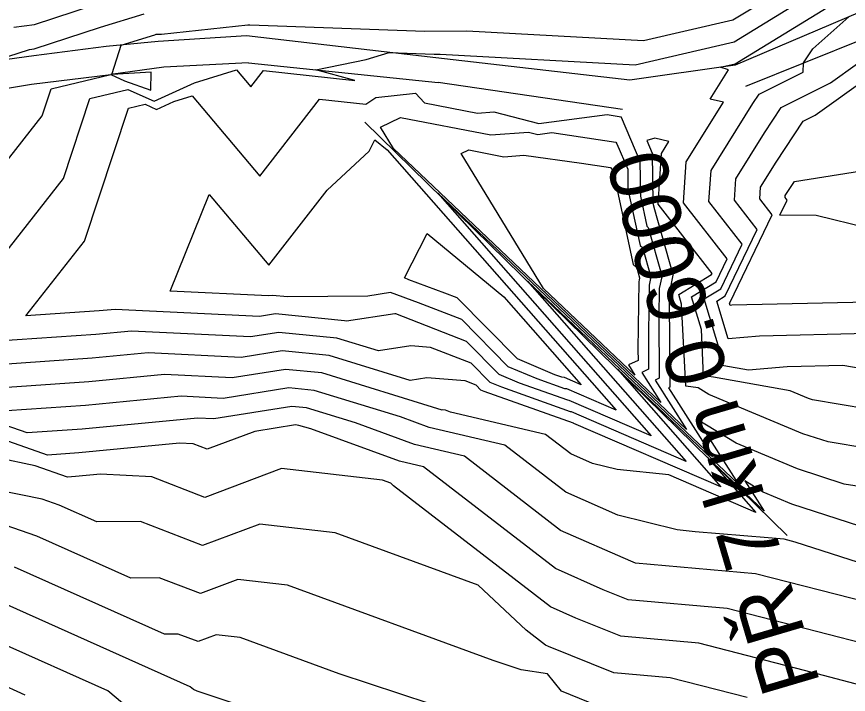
# Model space of a CAD drawing. Extents: x -549394 to -546608, y -1037055 to -1033629.
# Drawn here: x -547944.9 to -547816.2, y -1035642.2 to -1035537.3 of the extents above; entities that cross this region are included whole.
import ezdxf

# ---------------------------------------------------------------- set-up
doc = ezdxf.new("R2010")
doc.units = 0
for name, color, linetype in [('hlavni_vrst', 7, 'Continuous'), ('hrana_L', 7, 'Continuous'), ('norm_vrst', 7, 'Continuous'), ('x_popis_pricne_rezy_C1', 7, 'Continuous')]:
    doc.layers.add(name, color=color, linetype=linetype)

msp = doc.modelspace()

# ---------------------------------------------------------------- linework, layer by layer
at = {"layer": 'hlavni_vrst'}
for p, q in [((-547833.67, -1035544.62), (-547816.24, -1035533.92)), ((-547837.57, -1035550.06), (-547834.74, -1035545.54)), ((-547835.99, -1035545.15), (-547833.67, -1035544.62)), ((-547834.74, -1035545.54), (-547835.99, -1035545.15)), ((-547889.33, -1035549.83), (-547883.16, -1035549.18)), ((-547883.16, -1035549.18), (-547881.77, -1035550.67)), ((-547923.29, -1035551.66), (-547920.56, -1035550.43)), ((-547920.56, -1035550.43), (-547917.73, -1035549.55)), ((-547917.73, -1035549.55), (-547907.28, -1035562)), ((-547907.28, -1035562), (-547898.01, -1035550.06)), ((-547898.01, -1035550.06), (-547890.88, -1035550.84)), ((-547890.88, -1035550.84), (-547889.33, -1035549.83)), ((-547881.77, -1035550.67), (-547873.55, -1035552.25)), ((-547841.25, -1035559.8), (-547835.48, -1035550.56)), ((-547835.48, -1035550.56), (-547837.57, -1035550.06)), ((-547934.4, -1035572.05), (-547927.62, -1035551.49)), ((-547927.62, -1035551.49), (-547925.04, -1035550.88)), ((-547925.04, -1035550.88), (-547923.29, -1035551.66)), ((-547873.55, -1035552.25), (-547871.03, -1035552.06)), ((-547871.03, -1035552.06), (-547864.06, -1035553.84)), ((-547864.06, -1035553.84), (-547853.52, -1035552.48)), ((-547853.52, -1035552.48), (-547851.35, -1035552.8)), ((-547851.35, -1035552.8), (-547851.32, -1035552.85)), ((-547851.32, -1035552.85), (-547848.42, -1035559.69)), ((-547848.42, -1035559.69), (-547848.34, -1035565.11)), ((-547841.66, -1035566.13), (-547841.25, -1035559.8)), ((-547879.73, -1035564.66), (-547846.71, -1035602.21)), ((-547841.2, -1035601.24), (-547879.73, -1035564.66)), ((-547848.34, -1035565.11), (-547847.35, -1035569.75)), ((-547834.93, -1035574.81), (-547841.66, -1035566.13)), ((-547847.35, -1035569.75), (-547847.14, -1035569.93)), ((-547847.14, -1035569.93), (-547845.03, -1035577.41)), ((-547943.47, -1035583.64), (-547934.4, -1035572.05)), ((-547836.63, -1035578.35), (-547834.93, -1035574.81)), ((-547845.06, -1035577.58), (-547845.44, -1035579.42)), ((-547845.03, -1035577.41), (-547845.06, -1035577.58)), ((-547840.46, -1035580.67), (-547836.63, -1035578.35)), ((-547845.44, -1035579.42), (-547845.5, -1035583.76)), ((-547838.92, -1035585.75), (-547840.46, -1035580.67)), ((-547932.16, -1035582.87), (-547943.47, -1035583.64)), ((-547929.67, -1035582.63), (-547932.16, -1035582.87)), ((-547907.32, -1035583.73), (-547929.67, -1035582.63)), ((-547904.86, -1035583.34), (-547907.32, -1035583.73)), ((-547894.15, -1035584.38), (-547904.86, -1035583.34)), ((-547886.37, -1035583.33), (-547893.84, -1035584.47)), ((-547886.2, -1035583.34), (-547886.37, -1035583.33)), ((-547875.26, -1035587.6), (-547886.2, -1035583.34)), ((-547845.5, -1035583.76), (-547845.43, -1035593.29)), ((-547893.84, -1035584.47), (-547894.15, -1035584.38)), ((-547838.57, -1035592.92), (-547838.92, -1035585.75)), ((-547870.22, -1035592.72), (-547875.26, -1035587.6)), ((-547867.08, -1035594.05), (-547870.22, -1035592.72)), ((-547837.06, -1035593.12), (-547838.57, -1035592.92)), ((-547825.17, -1035595.25), (-547837.06, -1035593.12)), ((-547859.6, -1035596.71), (-547867.08, -1035594.05)), ((-547845.43, -1035593.29), (-547846.07, -1035593.6)), ((-547846.07, -1035593.6), (-547841.2, -1035601.24)), ((-547943.29, -1035601.77), (-547961.77, -1035595.29)), ((-547822.34, -1035596.43), (-547825.17, -1035595.25)), ((-547859.39, -1035596.73), (-547859.6, -1035596.71)), ((-547846.71, -1035602.21), (-547859.39, -1035596.73)), ((-547821.72, -1035596.64), (-547822.34, -1035596.43)), ((-547805.21, -1035599.43), (-547821.72, -1035596.64)), ((-547902.29, -1035597.67), (-547914.37, -1035599.58)), ((-547900.05, -1035597.88), (-547902.29, -1035597.67)), ((-547892.44, -1035600.22), (-547900.05, -1035597.88)), ((-547916.9, -1035599.46), (-547934.77, -1035601.19)), ((-547914.37, -1035599.58), (-547916.9, -1035599.46)), ((-547883.35, -1035603.53), (-547892.44, -1035600.22)), ((-547934.77, -1035601.19), (-547943.29, -1035601.77)), ((-547875.61, -1035605.34), (-547883.35, -1035603.53)), ((-547860.7, -1035616.85), (-547875.61, -1035605.34)), ((-547849.86, -1035621.63), (-547860.7, -1035616.85)), ((-547922.03, -1035632.93), (-547945.25, -1035622.54)), ((-547849.11, -1035621.93), (-547849.86, -1035621.63)), ((-547830.53, -1035623.58), (-547849.11, -1035621.93)), ((-547812.93, -1035628.1), (-547830.53, -1035623.58)), ((-547919.9, -1035632.9), (-547922.03, -1035632.93)), ((-547916.84, -1035634.08), (-547919.9, -1035632.9)), ((-547914.03, -1035633.03), (-547916.84, -1035634.08)), ((-547910.33, -1035633.46), (-547914.03, -1035633.03)), ((-547895, -1035639.08), (-547910.33, -1035633.46)), ((-547876.12, -1035645.25), (-547895, -1035639.08))]:
    msp.add_line(p, q, dxfattribs=at)
at = {"layer": 'hrana_L'}
for p, q in [((-547814.39, -1035536.61), (-547833.66, -1035544.82)), ((-547909.34, -1035540.3), (-547923, -1035541.16)), ((-547880.04, -1035543.67), (-547909.34, -1035540.3)), ((-547923, -1035541.16), (-547931.07, -1035541.92)), ((-547832.01, -1035548.06), (-547813.58, -1035540.62)), ((-547931.07, -1035541.92), (-547942.25, -1035543.35)), ((-547942.25, -1035543.35), (-547972.47, -1035547.64)), ((-547849.99, -1035547.16), (-547880.04, -1035543.67)), ((-547922.15, -1035545.14), (-547930.35, -1035546.27)), ((-547909.02, -1035544.46), (-547922.15, -1035545.14)), ((-547909.02, -1035544.46), (-547879.65, -1035547.5)), ((-547833.66, -1035544.82), (-547849.99, -1035547.16)), ((-547942.64, -1035547.74), (-547930.35, -1035546.27)), ((-547971.54, -1035552.66), (-547942.64, -1035547.74)), ((-547851.13, -1035551.7), (-547879.65, -1035547.5)), ((-547890.99, -1035553.63), (-547825.64, -1035617.62))]:
    msp.add_line(p, q, dxfattribs=at)
at = {"layer": 'norm_vrst'}
for p, q in [((-547834.04, -1035537.81), (-547819.64, -1035528.97)), ((-547833.85, -1035541.21), (-547817.94, -1035531.44)), ((-547942.17, -1035538.52), (-547932.88, -1035535.5)), ((-547931.91, -1035538.93), (-547925.16, -1035536.89)), ((-547847.89, -1035541.02), (-547834.04, -1035537.81)), ((-547821.64, -1035542.31), (-547816.07, -1035537.33)), ((-547945.36, -1035538.96), (-547942.17, -1035538.52)), ((-547942.23, -1035542.29), (-547931.91, -1035538.93)), ((-547922.51, -1035540.04), (-547909.14, -1035538.57)), ((-547909.14, -1035538.57), (-547908.8, -1035538.55)), ((-547908.8, -1035538.55), (-547881.74, -1035539.58)), ((-547928.74, -1035541.7), (-547923.52, -1035540.13)), ((-547923.52, -1035540.13), (-547923.31, -1035540.03)), ((-547923.31, -1035540.03), (-547922.51, -1035540.04)), ((-547881.74, -1035539.58), (-547875.22, -1035539.51)), ((-547875.22, -1035539.51), (-547847.89, -1035541.02)), ((-547849.17, -1035544.77), (-547833.85, -1035541.21)), ((-547948.71, -1035544.27), (-547942.93, -1035542.39)), ((-547942.93, -1035542.39), (-547942.23, -1035542.29)), ((-547930.13, -1035546.12), (-547928.74, -1035541.7)), ((-547890.82, -1035543.96), (-547887.25, -1035542.84)), ((-547887.25, -1035542.84), (-547880.27, -1035543.11)), ((-547823.1, -1035544.46), (-547821.64, -1035542.31)), ((-547898.59, -1035545.54), (-547890.82, -1035543.96)), ((-547880.27, -1035543.11), (-547879.37, -1035543.1)), ((-547879.37, -1035543.1), (-547849.17, -1035544.77)), ((-547917.38, -1035547.56), (-547910.87, -1035545.54)), ((-547910.87, -1035545.54), (-547908.65, -1035548.19)), ((-547892.57, -1035547.19), (-547898.59, -1035545.54)), ((-547823.16, -1035545.88), (-547823.1, -1035544.46)), ((-547821.28, -1035552.58), (-547810.32, -1035544.67)), ((-547818.92, -1035547.58), (-547814.73, -1035544.55)), ((-547939.59, -1035548.5), (-547930.32, -1035546.29)), ((-547930.32, -1035546.29), (-547928.24, -1035547.23)), ((-547930.12, -1035546.24), (-547930.13, -1035546.12)), ((-547924.1, -1035545.88), (-547930.12, -1035546.24)), ((-547924.12, -1035548.71), (-547924.1, -1035545.88)), ((-547908.65, -1035548.19), (-547906.68, -1035545.65)), ((-547906.68, -1035545.65), (-547892.57, -1035547.19)), ((-547829.99, -1035549.3), (-547823.16, -1035545.88)), ((-547928.24, -1035547.23), (-547924.12, -1035548.71)), ((-547923.65, -1035550.39), (-547917.38, -1035547.56)), ((-547826.56, -1035551.4), (-547818.92, -1035547.58)), ((-547940.97, -1035552.68), (-547939.59, -1035548.5)), ((-547933.6, -1035550), (-547927.68, -1035548.58)), ((-547927.68, -1035548.58), (-547923.65, -1035550.39)), ((-547830.95, -1035550.75), (-547829.99, -1035549.3)), ((-547937.68, -1035562.37), (-547933.6, -1035550)), ((-547837.42, -1035561.11), (-547830.95, -1035550.75)), ((-547829.15, -1035555.3), (-547826.56, -1035551.4)), ((-547946.89, -1035560.24), (-547940.97, -1035552.68)), ((-547888.61, -1035554.41), (-547885.5, -1035552.93)), ((-547885.5, -1035552.93), (-547871.52, -1035555.62)), ((-547823.14, -1035553.51), (-547821.28, -1035552.58)), ((-547886.58, -1035557.74), (-547888.61, -1035554.41)), ((-547827.35, -1035559.85), (-547823.14, -1035553.51)), ((-547871.52, -1035555.62), (-547865.67, -1035555.19)), ((-547865.67, -1035555.19), (-547864.24, -1035555.55)), ((-547864.24, -1035555.55), (-547862.06, -1035555.27)), ((-547862.06, -1035555.27), (-547852.16, -1035556.74)), ((-547833.6, -1035562.41), (-547829.15, -1035555.3)), ((-547890.33, -1035558.11), (-547889.45, -1035556.38)), ((-547889.45, -1035556.38), (-547887.56, -1035557.95)), ((-547852.16, -1035556.74), (-547851.99, -1035556.98)), ((-547851.99, -1035556.98), (-547850.32, -1035560.9)), ((-547846.12, -1035556.12), (-547847.35, -1035556.5)), ((-547847.35, -1035556.5), (-547846.52, -1035558.47)), ((-547843.93, -1035556.65), (-547846.12, -1035556.12)), ((-547845.08, -1035558.5), (-547843.93, -1035556.65)), ((-547896.86, -1035564.16), (-547890.33, -1035558.11)), ((-547887.56, -1035557.95), (-547852.12, -1035598.25)), ((-547845.2, -1035597.03), (-547886.58, -1035557.74)), ((-547876.09, -1035558.52), (-547874.89, -1035557.95)), ((-547874.89, -1035557.95), (-547869.48, -1035558.99)), ((-547863.36, -1035579.38), (-547876.09, -1035558.52)), ((-547869.48, -1035558.99), (-547866.4, -1035558.76)), ((-547866.4, -1035558.76), (-547857.46, -1035560.01)), ((-547846.52, -1035558.47), (-547846.41, -1035566.21)), ((-547845.59, -1035566.33), (-547845.08, -1035558.5)), ((-547857.46, -1035560.01), (-547852.96, -1035560.68)), ((-547852.96, -1035560.68), (-547852.66, -1035561.1)), ((-547850.32, -1035560.9), (-547850.28, -1035564.02)), ((-547829.77, -1035563.72), (-547827.35, -1035559.85)), ((-547824.52, -1035562.85), (-547809.54, -1035560.47)), ((-547852.66, -1035561.1), (-547852.22, -1035562.12)), ((-547852.22, -1035562.12), (-547852.21, -1035562.92)), ((-547837.74, -1035565.92), (-547837.42, -1035561.11)), ((-547955.22, -1035584.76), (-547937.68, -1035562.37)), ((-547852.21, -1035562.92), (-547849.47, -1035575.7)), ((-547833.81, -1035565.72), (-547833.6, -1035562.41)), ((-547825.55, -1035564.4), (-547824.52, -1035562.85)), ((-547921.14, -1035579.81), (-547915.12, -1035564.83)), ((-547915.12, -1035564.83), (-547905.9, -1035575.8)), ((-547905.9, -1035575.8), (-547896.86, -1035564.16)), ((-547850.28, -1035564.02), (-547848.41, -1035572.73)), ((-547829.88, -1035565.51), (-547829.77, -1035563.72)), ((-547825.94, -1035565.02), (-547825.55, -1035564.4)), ((-547832.61, -1035572.53), (-547837.74, -1035565.92)), ((-547830.29, -1035570.26), (-547833.81, -1035565.72)), ((-547827.97, -1035567.98), (-547829.88, -1035565.51)), ((-547826.77, -1035568.03), (-547825.65, -1035565.7)), ((-547825.96, -1035565.31), (-547825.94, -1035565.02)), ((-547825.65, -1035565.7), (-547825.96, -1035565.31)), ((-547846.41, -1035566.21), (-547846.29, -1035566.78)), ((-547846.29, -1035566.78), (-547846.26, -1035566.8)), ((-547846.26, -1035566.8), (-547843.31, -1035577.25)), ((-547837.25, -1035577.09), (-547845.59, -1035566.33)), ((-547834.5, -1035581.64), (-547827.97, -1035567.98)), ((-547821.16, -1035568.08), (-547826.77, -1035568.03)), ((-547799.43, -1035573.39), (-547821.16, -1035568.08)), ((-547884.85, -1035577.74), (-547881.35, -1035570.87)), ((-547881.35, -1035570.87), (-547869.51, -1035580.68)), ((-547835.21, -1035580.55), (-547830.29, -1035570.26)), ((-547835.92, -1035579.45), (-547832.61, -1035572.53)), ((-547848.41, -1035572.73), (-547848.02, -1035573.07)), ((-547848.02, -1035573.07), (-547846.75, -1035577.58)), ((-547849.47, -1035575.7), (-547848.9, -1035576.2)), ((-547848.9, -1035576.2), (-547848.47, -1035577.74)), ((-547884.22, -1035578.06), (-547884.85, -1035577.74)), ((-547848.47, -1035577.74), (-547848.53, -1035578.11)), ((-547846.75, -1035577.58), (-547846.8, -1035577.84)), ((-547843.33, -1035577.31), (-547843.86, -1035579.97)), ((-547843.31, -1035577.25), (-547843.33, -1035577.31)), ((-547842.42, -1035580.33), (-547837.33, -1035577.25)), ((-547837.33, -1035577.25), (-547837.25, -1035577.09)), ((-547878.63, -1035580.1), (-547884.22, -1035578.06)), ((-547865.82, -1035578.27), (-547841.29, -1035606.17)), ((-547837.2, -1035605.45), (-547865.82, -1035578.27)), ((-547848.58, -1035578.33), (-547848.74, -1035588.82)), ((-547848.53, -1035578.11), (-547848.58, -1035578.33)), ((-547847.01, -1035578.88), (-547847.12, -1035586.29)), ((-547846.8, -1035577.84), (-547847.01, -1035578.88)), ((-547905.91, -1035580.56), (-547921.14, -1035579.81)), ((-547887.03, -1035580.03), (-547890.54, -1035580.58)), ((-547882.7, -1035581.61), (-547887.03, -1035580.03)), ((-547876.71, -1035580.84), (-547878.63, -1035580.1)), ((-547849.2, -1035592.82), (-547863.36, -1035579.38)), ((-547843.86, -1035579.97), (-547843.88, -1035581.23)), ((-547838.5, -1035581.01), (-547835.92, -1035579.45)), ((-547905.38, -1035580.47), (-547905.91, -1035580.56)), ((-547902.92, -1035580.71), (-547905.38, -1035580.47)), ((-547890.54, -1035580.58), (-547902.92, -1035580.71)), ((-547875.98, -1035584.22), (-547882.7, -1035581.61)), ((-547867.4, -1035590.31), (-547876.71, -1035580.84)), ((-547869.51, -1035580.68), (-547857.54, -1035594.29)), ((-547843.88, -1035581.23), (-547843.78, -1035594.66)), ((-547841.97, -1035581.81), (-547842.42, -1035580.33)), ((-547835.87, -1035589.7), (-547838.5, -1035581.01)), ((-547836.54, -1035581.35), (-547835.21, -1035580.55)), ((-547834.78, -1035587.18), (-547836.54, -1035581.35)), ((-547804.25, -1035581.28), (-547834.2, -1035582)), ((-547841.34, -1035594.53), (-547841.97, -1035581.81)), ((-547834.58, -1035581.69), (-547834.5, -1035581.64)), ((-547834.48, -1035582.02), (-547834.58, -1035581.69)), ((-547834.2, -1035582), (-547834.48, -1035582.02)), ((-547868.81, -1035591.52), (-547875.98, -1035584.22)), ((-547932.68, -1035586.53), (-547955.84, -1035588.11)), ((-547927.12, -1035585.99), (-547932.68, -1035586.53)), ((-547908.73, -1035586.9), (-547927.12, -1035585.99)), ((-547904.35, -1035586.2), (-547908.73, -1035586.9)), ((-547895.33, -1035587.08), (-547904.35, -1035586.2)), ((-547847.12, -1035586.29), (-547847.08, -1035591.91)), ((-547810.63, -1035586.31), (-547829.92, -1035586.77)), ((-547888.9, -1035589.05), (-547895.33, -1035587.08)), ((-547829.92, -1035586.77), (-547834.78, -1035587.18)), ((-547903.83, -1035589.07), (-547910.14, -1035590.07)), ((-547896.51, -1035589.78), (-547903.83, -1035589.07)), ((-547883.89, -1035588.29), (-547888.9, -1035589.05)), ((-547880.83, -1035588.52), (-547883.89, -1035588.29)), ((-547874.53, -1035590.98), (-547880.83, -1035588.52)), ((-547848.74, -1035588.82), (-547848.72, -1035590.54)), ((-547933.2, -1035590.2), (-547952.71, -1035591.53)), ((-547924.56, -1035589.36), (-547933.2, -1035590.2)), ((-547910.14, -1035590.07), (-547924.56, -1035589.36)), ((-547883.97, -1035593.63), (-547896.51, -1035589.78)), ((-547861.6, -1035592.76), (-547867.4, -1035590.31)), ((-547848.72, -1035590.54), (-547850.21, -1035591.24)), ((-547835.79, -1035591.31), (-547835.87, -1035589.7)), ((-547871.62, -1035593.93), (-547874.53, -1035590.98)), ((-547864.34, -1035593.4), (-547868.81, -1035591.52)), ((-547851.92, -1035591.89), (-547835.88, -1035610.13)), ((-547833.2, -1035609.66), (-547851.92, -1035591.89)), ((-547850.21, -1035591.24), (-547849.2, -1035592.82)), ((-547847.08, -1035591.91), (-547848.14, -1035592.42)), ((-547835.46, -1035591.35), (-547835.79, -1035591.31)), ((-547831.61, -1035592.04), (-547835.46, -1035591.35)), ((-547825.65, -1035591.54), (-547831.61, -1035592.04)), ((-547817.01, -1035591.33), (-547825.65, -1035591.54)), ((-547804.58, -1035593.43), (-547817.01, -1035591.33)), ((-547922.01, -1035592.72), (-547933.72, -1035593.86)), ((-547911.55, -1035593.24), (-547922.01, -1035592.72)), ((-547903.32, -1035591.94), (-547911.55, -1035593.24)), ((-547897.69, -1035592.48), (-547903.32, -1035591.94)), ((-547879.03, -1035598.22), (-547897.69, -1035592.48)), ((-547860.52, -1035593.15), (-547861.6, -1035592.76)), ((-547860.12, -1035593.18), (-547860.52, -1035593.15)), ((-547857.54, -1035594.29), (-547860.12, -1035593.18)), ((-547848.14, -1035592.42), (-547845.2, -1035597.03)), ((-547933.72, -1035593.86), (-547949.57, -1035594.94)), ((-547881.41, -1035593.24), (-547883.97, -1035593.63)), ((-547875.47, -1035593.7), (-547881.41, -1035593.24)), ((-547873.8, -1035594.35), (-547875.47, -1035593.7)), ((-547873.03, -1035595.14), (-547873.8, -1035594.35)), ((-547869.82, -1035594.69), (-547871.62, -1035593.93)), ((-547860.06, -1035594.93), (-547864.34, -1035593.4)), ((-547902.8, -1035594.8), (-547912.96, -1035596.41)), ((-547898.87, -1035595.18), (-547902.8, -1035594.8)), ((-547885.5, -1035599.29), (-547898.87, -1035595.18)), ((-547872.55, -1035595.34), (-547873.03, -1035595.14)), ((-547858.69, -1035600.27), (-547872.55, -1035595.34)), ((-547859.15, -1035598.49), (-547869.82, -1035594.69)), ((-547859.75, -1035594.95), (-547860.06, -1035594.93)), ((-547852.12, -1035598.25), (-547859.75, -1035594.95)), ((-547843.78, -1035594.66), (-547844.01, -1035594.77)), ((-547844.01, -1035594.77), (-547837.2, -1035605.45)), ((-547839.42, -1035594.79), (-547841.34, -1035594.53)), ((-547837.74, -1035595.82), (-547839.42, -1035594.79)), ((-547919.46, -1035596.09), (-547934.25, -1035597.53)), ((-547912.96, -1035596.41), (-547919.46, -1035596.09)), ((-547823.19, -1035601.88), (-547837.74, -1035595.82)), ((-547940.15, -1035605.19), (-547960.36, -1035598.09)), ((-547934.25, -1035597.53), (-547946.43, -1035598.36)), ((-547878.93, -1035598.2), (-547879.03, -1035598.22)), ((-547878.52, -1035598.23), (-547878.93, -1035598.2)), ((-547877.75, -1035598.53), (-547878.52, -1035598.23)), ((-547881.04, -1035600.91), (-547885.5, -1035599.29)), ((-547863.03, -1035601.98), (-547877.75, -1035598.53)), ((-547859.03, -1035598.5), (-547859.15, -1035598.49)), ((-547841.29, -1035606.17), (-547859.03, -1035598.5)), ((-547901.77, -1035600.53), (-547908.04, -1035601.53)), ((-547901.23, -1035600.59), (-547901.77, -1035600.53)), ((-547899.39, -1035601.15), (-547901.23, -1035600.59)), ((-547869.32, -1035603.66), (-547881.04, -1035600.91)), ((-547858.67, -1035600.28), (-547858.69, -1035600.27)), ((-547835.88, -1035610.13), (-547858.67, -1035600.28)), ((-547833.55, -1035603.36), (-547839.56, -1035599.69)), ((-547839.56, -1035599.69), (-547833.2, -1035609.66)), ((-547908.04, -1035601.53), (-547915.4, -1035604.29)), ((-547885.65, -1035606.14), (-547899.39, -1035601.15)), ((-547859.12, -1035605), (-547863.03, -1035601.98)), ((-547819.27, -1035603.15), (-547823.19, -1035601.88)), ((-547942.03, -1035606.84), (-547962.15, -1035602.69)), ((-547919.68, -1035603.34), (-547935.29, -1035604.86)), ((-547917.58, -1035603.45), (-547919.68, -1035603.34)), ((-547915.4, -1035604.29), (-547917.58, -1035603.45)), ((-547824.04, -1035607.33), (-547833.55, -1035603.36)), ((-547805.84, -1035605.43), (-547819.27, -1035603.15)), ((-547859.91, -1035610.92), (-547869.32, -1035603.66)), ((-547935.29, -1035604.86), (-547940.15, -1035605.19)), ((-547855.77, -1035606.48), (-547859.12, -1035605)), ((-547838.01, -1035605.5), (-547830.46, -1035614.09)), ((-547829.2, -1035613.87), (-547838.01, -1035605.5)), ((-547937.02, -1035608.6), (-547942.03, -1035606.84)), ((-547903.91, -1035607.29), (-547915.76, -1035611.74)), ((-547888.26, -1035609.09), (-547903.91, -1035607.29)), ((-547881.91, -1035607.02), (-547885.65, -1035606.14)), ((-547861.48, -1035622.77), (-547881.91, -1035607.02)), ((-547851.96, -1035607.43), (-547855.77, -1035606.48)), ((-547816.83, -1035609.67), (-547824.04, -1035607.33)), ((-547940.97, -1035612.03), (-547961.47, -1035607.8)), ((-547935.81, -1035608.52), (-547937.02, -1035608.6)), ((-547931.94, -1035608.14), (-547935.81, -1035608.52)), ((-547924.01, -1035608.55), (-547931.94, -1035608.14)), ((-547915.76, -1035611.74), (-547924.01, -1035608.55)), ((-547843.95, -1035608.26), (-547851.96, -1035607.43)), ((-547830.46, -1035614.09), (-547843.95, -1035608.26)), ((-547887.01, -1035609.55), (-547888.26, -1035609.09)), ((-547886.59, -1035609.94), (-547887.01, -1035609.55)), ((-547829.37, -1035610.91), (-547832.19, -1035609.18)), ((-547832.19, -1035609.18), (-547829.2, -1035613.87)), ((-547806.46, -1035611.42), (-547816.83, -1035609.67)), ((-547862.27, -1035628.7), (-547886.59, -1035609.94)), ((-547851.83, -1035614.48), (-547859.91, -1035610.92)), ((-547824.89, -1035612.77), (-547829.37, -1035610.91)), ((-547938.31, -1035612.95), (-547940.97, -1035612.03)), ((-547932.48, -1035615.55), (-547938.31, -1035612.95)), ((-547814.39, -1035616.18), (-547824.89, -1035612.77)), ((-547842.66, -1035616.77), (-547851.83, -1035614.48)), ((-547941.78, -1035617.74), (-547948.42, -1035615.46)), ((-547925.76, -1035615.46), (-547932.48, -1035615.55)), ((-547916.12, -1035619.19), (-547925.76, -1035615.46)), ((-547907.28, -1035615.87), (-547916.12, -1035619.19)), ((-547895.62, -1035617.21), (-547907.28, -1035615.87)), ((-547873.48, -1035625.33), (-547895.62, -1035617.21)), ((-547839.88, -1035617.06), (-547842.66, -1035616.77)), ((-547828.57, -1035617.99), (-547839.88, -1035617.06)), ((-547927.25, -1035624.24), (-547941.78, -1035617.74)), ((-547826.12, -1035618.21), (-547828.57, -1035617.99)), ((-547824.38, -1035618.66), (-547826.12, -1035618.21)), ((-547811.95, -1035622.7), (-547824.38, -1035618.66)), ((-547854.1, -1035626.03), (-547861.48, -1035622.77)), ((-547922.83, -1035624.18), (-547927.25, -1035624.24)), ((-547916.48, -1035626.64), (-547922.83, -1035624.18)), ((-547910.66, -1035624.45), (-547916.48, -1035626.64)), ((-547902.97, -1035625.33), (-547910.66, -1035624.45)), ((-547871.16, -1035637), (-547902.97, -1035625.33)), ((-547866.05, -1035632.32), (-547873.48, -1035625.33)), ((-547850.24, -1035627.59), (-547854.1, -1035626.03)), ((-547918.06, -1035641.06), (-547948.72, -1035627.34)), ((-547834.93, -1035628.95), (-547850.24, -1035627.59)), ((-547858.34, -1035630.43), (-547862.27, -1035628.7)), ((-547814.08, -1035634.31), (-547834.93, -1035628.95)), ((-547851.36, -1035633.25), (-547858.34, -1035630.43)), ((-547930.82, -1035641.7), (-547952.19, -1035632.14)), ((-547863.06, -1035634.62), (-547866.05, -1035632.32)), ((-547839.33, -1035634.32), (-547851.36, -1035633.25)), ((-547822.95, -1035638.53), (-547839.33, -1035634.32)), ((-547862.58, -1035634.83), (-547863.06, -1035634.62)), ((-547852.49, -1035638.91), (-547862.58, -1035634.83)), ((-547943.58, -1035642.34), (-547955.66, -1035636.94)), ((-547866.8, -1035638.43), (-547871.16, -1035637)), ((-547862.71, -1035639.07), (-547866.8, -1035638.43)), ((-547860.56, -1035641.77), (-547862.71, -1035639.07)), ((-547843.73, -1035639.69), (-547852.49, -1035638.91)), ((-547810.7, -1035641.76), (-547822.95, -1035638.53)), ((-547831.81, -1035642.75), (-547843.73, -1035639.69)), ((-547922.94, -1035648.21), (-547930.82, -1035641.7)), ((-547917.55, -1035641.48), (-547918.06, -1035641.06)), ((-547916.99, -1035641.76), (-547917.55, -1035641.48)), ((-547885.43, -1035652.08), (-547916.99, -1035641.76)), ((-547853.61, -1035644.58), (-547860.56, -1035641.77))]:
    msp.add_line(p, q, dxfattribs=at)

# ---------------------------------------------------------------- texts
at = {"layer": 'x_popis_pricne_rezy_C1'}
msp.add_text('PŘ 7 km 0.6000', height=9.0627, rotation=106.4623, dxfattribs=at).set_placement((-547820.47, -1035640.52))

doc.saveas('drawing.dxf')
